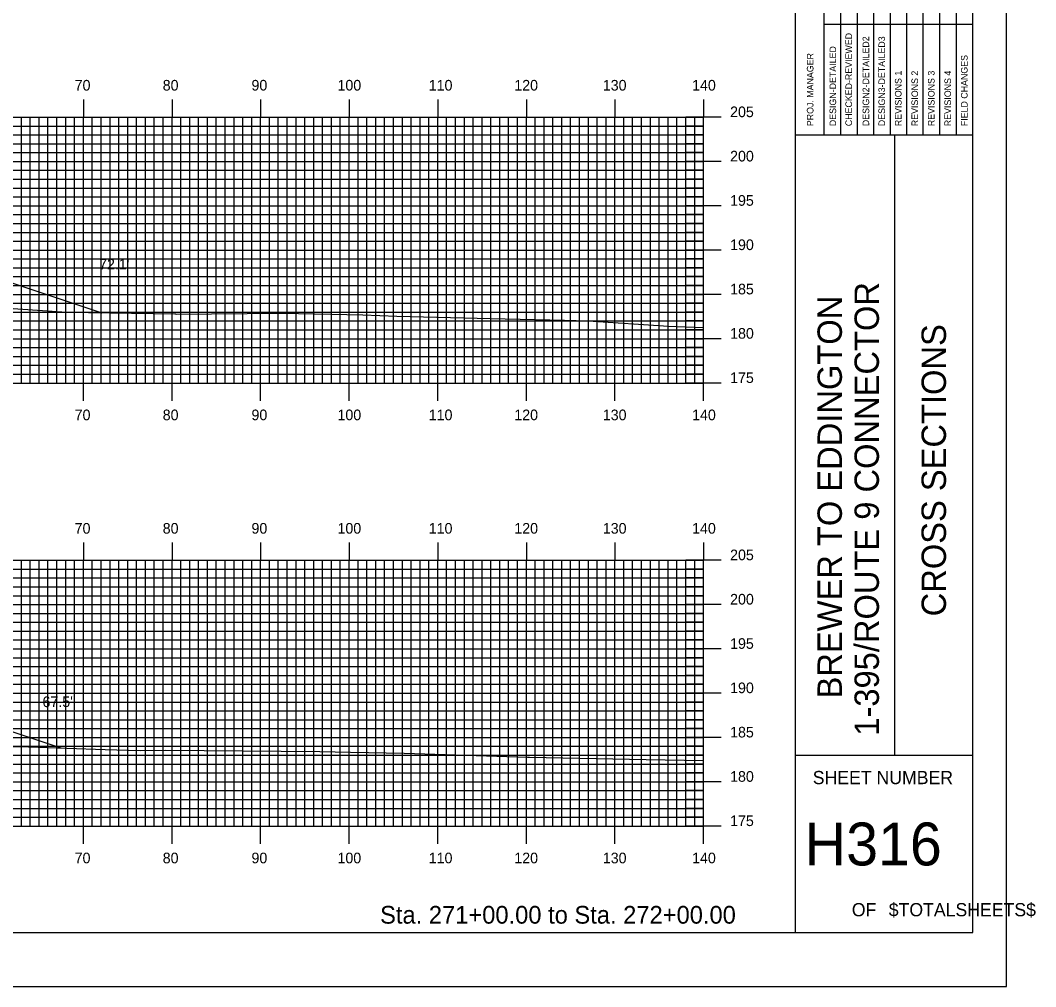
# Model space of a CAD drawing. Extents: x 1808619 to 1808962, y 442591 to 442811.
# Drawn here: x 1808847.7 to 1808962.3, y 442590.5 to 442699.6 of the extents above; entities that cross this region are included whole.
import ezdxf

# ---------------------------------------------------------------- set-up
doc = ezdxf.new("R2010")
doc.units = 0
for name, color, linetype in [('BORDER', 7, 'Continuous'), ('D_Roadway_Centerline', 7, 'Continuous'), ('D_Roadway_SlopeLines', 7, 'Continuous'), ('D_Text_Standard', 7, 'Continuous'), ('H_V ANNOTATION', 7, 'Continuous'), ('MAJOR', 7, 'Continuous'), ('MINOR', 7, 'Continuous'), ('PLOT BOUNDARY', 7, 'Continuous'), ('S_Roadway_Centerline', 7, 'Continuous')]:
    doc.layers.add(name, color=color, linetype=linetype)

msp = doc.modelspace()

# ---------------------------------------------------------------- linework, layer by layer
at = {"layer": 'BORDER'}
for p, q in [((1808935.21, 442596.67), (1808935.21, 442806.67)), ((1808935.21, 442686.67), (1808955.21, 442686.67)), ((1808946.39, 442616.67), (1808946.39, 442686.67)), ((1808935.21, 442616.67), (1808955.21, 442616.67))]:
    msp.add_line(p, q, dxfattribs=at)
msp.add_lwpolyline([(1808635.21, 442596.67), (1808955.21, 442596.67), (1808955.21, 442806.67), (1808635.21, 442806.67)], close=True, dxfattribs=at)
for points in [[(1808940.31, 442686.68), (1808940.31, 442721.67)], [(1808942.17, 442721.67), (1808942.17, 442686.68)], [(1808944.03, 442686.68), (1808944.03, 442721.67)], [(1808945.9, 442686.68), (1808945.9, 442721.67)], [(1808947.76, 442686.68), (1808947.76, 442721.67)], [(1808949.62, 442686.68), (1808949.62, 442721.67)], [(1808951.49, 442686.68), (1808951.49, 442721.67)], [(1808953.35, 442686.68), (1808953.35, 442721.67)], [(1808938.44, 442686.68), (1808938.44, 442720.26)], [(1808938.44, 442699.17), (1808955.21, 442699.17)]]:
    msp.add_lwpolyline(points, dxfattribs=at)
at = {"layer": 'D_Roadway_Centerline'}
for points in [[(1808717.59, 442667.84), (1808754.72, 442680.52), (1808761.81, 442682.94), (1808764.81, 442683.06), (1808772.81, 442683.38), (1808784.81, 442683.62), (1808796.81, 442683.38), (1808804.81, 442683.06), (1808807.81, 442682.94), (1808815.09, 442680.52), (1808856.88, 442666.59)], [(1808713.91, 442618.99), (1808744.23, 442629.09), (1808746.8, 442629.73), (1808756.23, 442632.09), (1808772.81, 442632.75), (1808784.81, 442632.99), (1808796.81, 442632.75), (1808804.81, 442632.43), (1808807.81, 442632.31), (1808815.09, 442629.89), (1808852.27, 442617.49)]]:
    msp.add_lwpolyline(points, dxfattribs=at)
at = {"layer": 'D_Roadway_SlopeLines'}
for points in [[(1808807.81, 442682.94), (1808856.88, 442666.59)], [(1808807.81, 442632.31), (1808852.27, 442617.49)]]:
    msp.add_lwpolyline(points, dxfattribs=at)
at = {"layer": 'MAJOR'}
for p, q in [((1808854.81, 442690.67), (1808854.81, 442688.67)), ((1808864.81, 442690.67), (1808864.81, 442688.67)), ((1808874.81, 442690.67), (1808874.81, 442688.67)), ((1808884.81, 442690.67), (1808884.81, 442688.67)), ((1808894.81, 442690.67), (1808894.81, 442688.67)), ((1808904.81, 442690.67), (1808904.81, 442688.67)), ((1808914.81, 442690.67), (1808914.81, 442688.67)), ((1808924.81, 442690.67), (1808924.81, 442688.67)), ((1808644.81, 442688.67), (1808924.81, 442688.67)), ((1808644.81, 442688.67), (1808924.81, 442688.67)), ((1808854.81, 442658.67), (1808854.81, 442688.67)), ((1808864.81, 442658.67), (1808864.81, 442688.67)), ((1808874.81, 442658.67), (1808874.81, 442688.67)), ((1808884.81, 442658.67), (1808884.81, 442688.67)), ((1808894.81, 442658.67), (1808894.81, 442688.67)), ((1808904.81, 442658.67), (1808904.81, 442688.67)), ((1808914.81, 442658.67), (1808914.81, 442688.67)), ((1808926.82, 442688.67), (1808922.81, 442688.67)), ((1808924.81, 442658.67), (1808924.81, 442688.67)), ((1808924.81, 442658.67), (1808924.81, 442688.67)), ((1808644.81, 442683.67), (1808924.81, 442683.67)), ((1808926.82, 442683.67), (1808922.81, 442683.67)), ((1808644.81, 442678.67), (1808924.81, 442678.67)), ((1808926.82, 442678.67), (1808922.81, 442678.67)), ((1808644.81, 442673.67), (1808924.81, 442673.67)), ((1808926.82, 442673.67), (1808922.81, 442673.67)), ((1808644.81, 442668.67), (1808924.81, 442668.67)), ((1808926.82, 442668.67), (1808922.81, 442668.67)), ((1808644.81, 442663.67), (1808924.81, 442663.67)), ((1808926.82, 442663.67), (1808922.81, 442663.67)), ((1808644.81, 442658.67), (1808924.81, 442658.67)), ((1808644.81, 442658.67), (1808924.81, 442658.67)), ((1808854.81, 442656.66), (1808854.81, 442658.67)), ((1808864.81, 442656.66), (1808864.81, 442658.67)), ((1808874.81, 442656.66), (1808874.81, 442658.67)), ((1808884.81, 442656.66), (1808884.81, 442658.67)), ((1808894.81, 442656.66), (1808894.81, 442658.67)), ((1808904.81, 442656.66), (1808904.81, 442658.67)), ((1808914.81, 442656.66), (1808914.81, 442658.67)), ((1808926.82, 442658.67), (1808922.81, 442658.67)), ((1808924.81, 442656.66), (1808924.81, 442658.67)), ((1808854.81, 442640.67), (1808854.81, 442638.67)), ((1808864.81, 442640.67), (1808864.81, 442638.67)), ((1808874.81, 442640.67), (1808874.81, 442638.67)), ((1808884.81, 442640.67), (1808884.81, 442638.67)), ((1808894.81, 442640.67), (1808894.81, 442638.67)), ((1808904.81, 442640.67), (1808904.81, 442638.67)), ((1808914.81, 442640.67), (1808914.81, 442638.67)), ((1808924.81, 442640.67), (1808924.81, 442638.67)), ((1808644.81, 442638.67), (1808924.81, 442638.67)), ((1808644.81, 442638.67), (1808924.81, 442638.67)), ((1808854.81, 442608.67), (1808854.81, 442638.67)), ((1808864.81, 442608.67), (1808864.81, 442638.67)), ((1808874.81, 442608.67), (1808874.81, 442638.67)), ((1808884.81, 442608.67), (1808884.81, 442638.67)), ((1808894.81, 442608.67), (1808894.81, 442638.67)), ((1808904.81, 442608.67), (1808904.81, 442638.67)), ((1808914.81, 442608.67), (1808914.81, 442638.67)), ((1808926.82, 442638.67), (1808922.81, 442638.67)), ((1808924.81, 442608.67), (1808924.81, 442638.67)), ((1808924.81, 442608.67), (1808924.81, 442638.67)), ((1808644.81, 442633.67), (1808924.81, 442633.67)), ((1808926.82, 442633.67), (1808922.81, 442633.67)), ((1808644.81, 442628.67), (1808924.81, 442628.67)), ((1808926.82, 442628.67), (1808922.81, 442628.67)), ((1808644.81, 442623.67), (1808924.81, 442623.67)), ((1808926.82, 442623.67), (1808922.81, 442623.67)), ((1808644.81, 442618.67), (1808924.81, 442618.67)), ((1808926.82, 442618.67), (1808922.81, 442618.67)), ((1808644.81, 442613.67), (1808924.81, 442613.67)), ((1808926.82, 442613.67), (1808922.81, 442613.67)), ((1808644.81, 442608.67), (1808924.81, 442608.67)), ((1808644.81, 442608.67), (1808924.81, 442608.67)), ((1808854.81, 442606.66), (1808854.81, 442608.67)), ((1808864.81, 442606.66), (1808864.81, 442608.67)), ((1808874.81, 442606.66), (1808874.81, 442608.67)), ((1808884.81, 442606.66), (1808884.81, 442608.67)), ((1808894.81, 442606.66), (1808894.81, 442608.67)), ((1808904.81, 442606.66), (1808904.81, 442608.67)), ((1808914.81, 442606.66), (1808914.81, 442608.67)), ((1808926.82, 442608.67), (1808922.81, 442608.67)), ((1808924.81, 442606.66), (1808924.81, 442608.67))]:
    msp.add_line(p, q, dxfattribs=at)
at = {"layer": 'MINOR'}
for p, q in [((1808644.81, 442687.67), (1808924.81, 442687.67)), ((1808847.81, 442658.67), (1808847.81, 442688.67)), ((1808848.81, 442658.67), (1808848.81, 442688.67)), ((1808849.81, 442658.67), (1808849.81, 442688.67)), ((1808850.81, 442658.67), (1808850.81, 442688.67)), ((1808851.81, 442658.67), (1808851.81, 442688.67)), ((1808852.81, 442658.67), (1808852.81, 442688.67)), ((1808853.81, 442658.67), (1808853.81, 442688.67)), ((1808855.81, 442658.67), (1808855.81, 442688.67)), ((1808856.81, 442658.67), (1808856.81, 442688.67)), ((1808857.81, 442658.67), (1808857.81, 442688.67)), ((1808858.81, 442658.67), (1808858.81, 442688.67)), ((1808859.81, 442658.67), (1808859.81, 442688.67)), ((1808860.81, 442658.67), (1808860.81, 442688.67)), ((1808861.81, 442658.67), (1808861.81, 442688.67)), ((1808862.81, 442658.67), (1808862.81, 442688.67)), ((1808863.81, 442658.67), (1808863.81, 442688.67)), ((1808865.81, 442658.67), (1808865.81, 442688.67)), ((1808866.81, 442658.67), (1808866.81, 442688.67)), ((1808867.81, 442658.67), (1808867.81, 442688.67)), ((1808868.81, 442658.67), (1808868.81, 442688.67)), ((1808869.81, 442658.67), (1808869.81, 442688.67)), ((1808870.81, 442658.67), (1808870.81, 442688.67)), ((1808871.81, 442658.67), (1808871.81, 442688.67)), ((1808872.81, 442658.67), (1808872.81, 442688.67)), ((1808873.81, 442658.67), (1808873.81, 442688.67)), ((1808875.81, 442658.67), (1808875.81, 442688.67)), ((1808876.81, 442658.67), (1808876.81, 442688.67)), ((1808877.81, 442658.67), (1808877.81, 442688.67)), ((1808878.81, 442658.67), (1808878.81, 442688.67)), ((1808879.81, 442658.67), (1808879.81, 442688.67)), ((1808880.81, 442658.67), (1808880.81, 442688.67)), ((1808881.81, 442658.67), (1808881.81, 442688.67)), ((1808882.81, 442658.67), (1808882.81, 442688.67)), ((1808883.81, 442658.67), (1808883.81, 442688.67)), ((1808885.81, 442658.67), (1808885.81, 442688.67)), ((1808886.81, 442658.67), (1808886.81, 442688.67)), ((1808887.81, 442658.67), (1808887.81, 442688.67)), ((1808888.81, 442658.67), (1808888.81, 442688.67)), ((1808889.81, 442658.67), (1808889.81, 442688.67)), ((1808890.81, 442658.67), (1808890.81, 442688.67)), ((1808891.81, 442658.67), (1808891.81, 442688.67)), ((1808892.81, 442658.67), (1808892.81, 442688.67)), ((1808893.81, 442658.67), (1808893.81, 442688.67)), ((1808895.81, 442658.67), (1808895.81, 442688.67)), ((1808896.81, 442658.67), (1808896.81, 442688.67)), ((1808897.81, 442658.67), (1808897.81, 442688.67)), ((1808898.81, 442658.67), (1808898.81, 442688.67)), ((1808899.81, 442658.67), (1808899.81, 442688.67)), ((1808900.81, 442658.67), (1808900.81, 442688.67)), ((1808901.81, 442658.67), (1808901.81, 442688.67)), ((1808902.81, 442658.67), (1808902.81, 442688.67)), ((1808903.81, 442658.67), (1808903.81, 442688.67)), ((1808905.81, 442658.67), (1808905.81, 442688.67)), ((1808906.81, 442658.67), (1808906.81, 442688.67)), ((1808907.81, 442658.67), (1808907.81, 442688.67)), ((1808908.81, 442658.67), (1808908.81, 442688.67)), ((1808909.81, 442658.67), (1808909.81, 442688.67)), ((1808910.81, 442658.67), (1808910.81, 442688.67)), ((1808911.81, 442658.67), (1808911.81, 442688.67)), ((1808912.81, 442658.67), (1808912.81, 442688.67)), ((1808913.81, 442658.67), (1808913.81, 442688.67)), ((1808915.81, 442658.67), (1808915.81, 442688.67)), ((1808916.81, 442658.67), (1808916.81, 442688.67)), ((1808917.81, 442658.67), (1808917.81, 442688.67)), ((1808918.81, 442658.67), (1808918.81, 442688.67)), ((1808919.81, 442658.67), (1808919.81, 442688.67)), ((1808920.81, 442658.67), (1808920.81, 442688.67)), ((1808921.81, 442658.67), (1808921.81, 442688.67)), ((1808922.81, 442658.67), (1808922.81, 442688.67)), ((1808924.81, 442687.67), (1808922.81, 442687.67)), ((1808923.81, 442658.67), (1808923.81, 442688.67)), ((1808644.81, 442686.67), (1808924.81, 442686.67)), ((1808924.81, 442686.67), (1808922.81, 442686.67)), ((1808644.81, 442685.67), (1808924.81, 442685.67)), ((1808924.81, 442685.67), (1808922.81, 442685.67)), ((1808644.81, 442684.67), (1808924.81, 442684.67)), ((1808924.81, 442684.67), (1808922.81, 442684.67)), ((1808644.81, 442682.67), (1808924.81, 442682.67)), ((1808924.81, 442682.67), (1808922.81, 442682.67)), ((1808644.81, 442681.67), (1808924.81, 442681.67)), ((1808924.81, 442681.67), (1808922.81, 442681.67)), ((1808644.81, 442680.67), (1808924.81, 442680.67)), ((1808644.81, 442679.67), (1808924.81, 442679.67)), ((1808924.81, 442680.67), (1808922.81, 442680.67)), ((1808924.81, 442679.67), (1808922.81, 442679.67)), ((1808644.81, 442677.67), (1808924.81, 442677.67)), ((1808924.81, 442677.67), (1808922.81, 442677.67)), ((1808644.81, 442676.67), (1808924.81, 442676.67)), ((1808924.81, 442676.67), (1808922.81, 442676.67)), ((1808644.81, 442675.67), (1808924.81, 442675.67)), ((1808924.81, 442675.67), (1808922.81, 442675.67)), ((1808644.81, 442674.67), (1808924.81, 442674.67)), ((1808924.81, 442674.67), (1808922.81, 442674.67)), ((1808644.81, 442672.67), (1808924.81, 442672.67)), ((1808644.81, 442671.67), (1808924.81, 442671.67)), ((1808924.81, 442672.67), (1808922.81, 442672.67)), ((1808924.81, 442671.67), (1808922.81, 442671.67)), ((1808644.81, 442670.67), (1808924.81, 442670.67)), ((1808924.81, 442670.67), (1808922.81, 442670.67)), ((1808644.81, 442669.67), (1808924.81, 442669.67)), ((1808924.81, 442669.67), (1808922.81, 442669.67)), ((1808644.81, 442667.67), (1808924.81, 442667.67)), ((1808924.81, 442667.67), (1808922.81, 442667.67)), ((1808644.81, 442666.67), (1808924.81, 442666.67)), ((1808924.81, 442666.67), (1808922.81, 442666.67)), ((1808644.81, 442665.67), (1808924.81, 442665.67)), ((1808924.81, 442665.67), (1808922.81, 442665.67)), ((1808644.81, 442664.67), (1808924.81, 442664.67)), ((1808924.81, 442664.67), (1808922.81, 442664.67)), ((1808644.81, 442662.67), (1808924.81, 442662.67)), ((1808924.81, 442662.67), (1808922.81, 442662.67)), ((1808644.81, 442661.67), (1808924.81, 442661.67)), ((1808924.81, 442661.67), (1808922.81, 442661.67)), ((1808644.81, 442660.67), (1808924.81, 442660.67)), ((1808924.81, 442660.67), (1808922.81, 442660.67)), ((1808644.81, 442659.67), (1808924.81, 442659.67)), ((1808924.81, 442659.67), (1808922.81, 442659.67)), ((1808847.81, 442608.67), (1808847.81, 442638.67)), ((1808848.81, 442608.67), (1808848.81, 442638.67)), ((1808849.81, 442608.67), (1808849.81, 442638.67)), ((1808850.81, 442608.67), (1808850.81, 442638.67)), ((1808851.81, 442608.67), (1808851.81, 442638.67)), ((1808852.81, 442608.67), (1808852.81, 442638.67)), ((1808853.81, 442608.67), (1808853.81, 442638.67)), ((1808855.81, 442608.67), (1808855.81, 442638.67)), ((1808856.81, 442608.67), (1808856.81, 442638.67)), ((1808857.81, 442608.67), (1808857.81, 442638.67)), ((1808858.81, 442608.67), (1808858.81, 442638.67)), ((1808859.81, 442608.67), (1808859.81, 442638.67)), ((1808860.81, 442608.67), (1808860.81, 442638.67)), ((1808861.81, 442608.67), (1808861.81, 442638.67)), ((1808862.81, 442608.67), (1808862.81, 442638.67)), ((1808863.81, 442608.67), (1808863.81, 442638.67)), ((1808865.81, 442608.67), (1808865.81, 442638.67)), ((1808866.81, 442608.67), (1808866.81, 442638.67)), ((1808867.81, 442608.67), (1808867.81, 442638.67)), ((1808868.81, 442608.67), (1808868.81, 442638.67)), ((1808869.81, 442608.67), (1808869.81, 442638.67)), ((1808870.81, 442608.67), (1808870.81, 442638.67)), ((1808871.81, 442608.67), (1808871.81, 442638.67)), ((1808872.81, 442608.67), (1808872.81, 442638.67)), ((1808873.81, 442608.67), (1808873.81, 442638.67)), ((1808875.81, 442608.67), (1808875.81, 442638.67)), ((1808876.81, 442608.67), (1808876.81, 442638.67)), ((1808877.81, 442608.67), (1808877.81, 442638.67)), ((1808878.81, 442608.67), (1808878.81, 442638.67)), ((1808879.81, 442608.67), (1808879.81, 442638.67)), ((1808880.81, 442608.67), (1808880.81, 442638.67)), ((1808881.81, 442608.67), (1808881.81, 442638.67)), ((1808882.81, 442608.67), (1808882.81, 442638.67)), ((1808883.81, 442608.67), (1808883.81, 442638.67)), ((1808885.81, 442608.67), (1808885.81, 442638.67)), ((1808886.81, 442608.67), (1808886.81, 442638.67)), ((1808887.81, 442608.67), (1808887.81, 442638.67)), ((1808888.81, 442608.67), (1808888.81, 442638.67)), ((1808889.81, 442608.67), (1808889.81, 442638.67)), ((1808890.81, 442608.67), (1808890.81, 442638.67)), ((1808891.81, 442608.67), (1808891.81, 442638.67)), ((1808892.81, 442608.67), (1808892.81, 442638.67)), ((1808893.81, 442608.67), (1808893.81, 442638.67)), ((1808895.81, 442608.67), (1808895.81, 442638.67)), ((1808896.81, 442608.67), (1808896.81, 442638.67)), ((1808897.81, 442608.67), (1808897.81, 442638.67)), ((1808898.81, 442608.67), (1808898.81, 442638.67)), ((1808899.81, 442608.67), (1808899.81, 442638.67)), ((1808900.81, 442608.67), (1808900.81, 442638.67)), ((1808901.81, 442608.67), (1808901.81, 442638.67)), ((1808902.81, 442608.67), (1808902.81, 442638.67)), ((1808903.81, 442608.67), (1808903.81, 442638.67)), ((1808905.81, 442608.67), (1808905.81, 442638.67)), ((1808906.81, 442608.67), (1808906.81, 442638.67)), ((1808907.81, 442608.67), (1808907.81, 442638.67)), ((1808908.81, 442608.67), (1808908.81, 442638.67)), ((1808909.81, 442608.67), (1808909.81, 442638.67)), ((1808910.81, 442608.67), (1808910.81, 442638.67)), ((1808911.81, 442608.67), (1808911.81, 442638.67)), ((1808912.81, 442608.67), (1808912.81, 442638.67)), ((1808913.81, 442608.67), (1808913.81, 442638.67)), ((1808915.81, 442608.67), (1808915.81, 442638.67)), ((1808916.81, 442608.67), (1808916.81, 442638.67)), ((1808917.81, 442608.67), (1808917.81, 442638.67)), ((1808918.81, 442608.67), (1808918.81, 442638.67)), ((1808919.81, 442608.67), (1808919.81, 442638.67)), ((1808920.81, 442608.67), (1808920.81, 442638.67)), ((1808921.81, 442608.67), (1808921.81, 442638.67)), ((1808922.81, 442608.67), (1808922.81, 442638.67)), ((1808923.81, 442608.67), (1808923.81, 442638.67)), ((1808644.81, 442637.67), (1808924.81, 442637.67)), ((1808924.81, 442637.67), (1808922.81, 442637.67)), ((1808644.81, 442636.67), (1808924.81, 442636.67)), ((1808924.81, 442636.67), (1808922.81, 442636.67)), ((1808644.81, 442635.67), (1808924.81, 442635.67)), ((1808924.81, 442635.67), (1808922.81, 442635.67)), ((1808644.81, 442634.67), (1808924.81, 442634.67)), ((1808924.81, 442634.67), (1808922.81, 442634.67)), ((1808644.81, 442632.67), (1808924.81, 442632.67)), ((1808924.81, 442632.67), (1808922.81, 442632.67)), ((1808644.81, 442631.67), (1808924.81, 442631.67)), ((1808924.81, 442631.67), (1808922.81, 442631.67)), ((1808644.81, 442630.67), (1808924.81, 442630.67)), ((1808924.81, 442630.67), (1808922.81, 442630.67)), ((1808644.81, 442629.67), (1808924.81, 442629.67)), ((1808924.81, 442629.67), (1808922.81, 442629.67)), ((1808644.81, 442627.67), (1808924.81, 442627.67)), ((1808924.81, 442627.67), (1808922.81, 442627.67)), ((1808644.81, 442626.67), (1808924.81, 442626.67)), ((1808924.81, 442626.67), (1808922.81, 442626.67)), ((1808644.81, 442625.67), (1808924.81, 442625.67)), ((1808644.81, 442624.67), (1808924.81, 442624.67)), ((1808924.81, 442625.67), (1808922.81, 442625.67)), ((1808924.81, 442624.67), (1808922.81, 442624.67)), ((1808644.81, 442622.67), (1808924.81, 442622.67)), ((1808924.81, 442622.67), (1808922.81, 442622.67)), ((1808644.81, 442621.67), (1808924.81, 442621.67)), ((1808924.81, 442621.67), (1808922.81, 442621.67)), ((1808644.81, 442620.67), (1808924.81, 442620.67)), ((1808924.81, 442620.67), (1808922.81, 442620.67)), ((1808644.81, 442619.67), (1808924.81, 442619.67)), ((1808924.81, 442619.67), (1808922.81, 442619.67)), ((1808644.81, 442617.67), (1808924.81, 442617.67)), ((1808644.81, 442616.67), (1808924.81, 442616.67)), ((1808924.81, 442617.67), (1808922.81, 442617.67)), ((1808924.81, 442616.67), (1808922.81, 442616.67)), ((1808644.81, 442615.67), (1808924.81, 442615.67)), ((1808924.81, 442615.67), (1808922.81, 442615.67)), ((1808644.81, 442614.67), (1808924.81, 442614.67)), ((1808924.81, 442614.67), (1808922.81, 442614.67)), ((1808644.81, 442612.67), (1808924.81, 442612.67)), ((1808924.81, 442612.67), (1808922.81, 442612.67)), ((1808644.81, 442611.67), (1808924.81, 442611.67)), ((1808924.81, 442611.67), (1808922.81, 442611.67)), ((1808644.81, 442610.67), (1808924.81, 442610.67)), ((1808924.81, 442610.67), (1808922.81, 442610.67)), ((1808644.81, 442609.67), (1808924.81, 442609.67)), ((1808924.81, 442609.67), (1808922.81, 442609.67))]:
    msp.add_line(p, q, dxfattribs=at)
at = {"layer": 'PLOT BOUNDARY'}
msp.add_lwpolyline([(1808619.02, 442590.55), (1808959.02, 442590.55), (1808959.02, 442810.55), (1808619.02, 442810.55)], close=True, dxfattribs=at)
at = {"layer": 'S_Roadway_Centerline'}
for points in [[(1808844.63, 442667.21), (1808852.92, 442666.65), (1808865.12, 442666.46), (1808865.21, 442666.46), (1808865.28, 442666.45), (1808877.28, 442666.55), (1808886.34, 442666.37), (1808890.19, 442666.21), (1808900.77, 442665.96), (1808909.12, 442665.76), (1808911.79, 442665.69), (1808920.85, 442665.07), (1808924.81, 442664.94)], [(1808842.48, 442617.66), (1808848.6, 442617.62), (1808857.25, 442617.32), (1808861.21, 442617.19), (1808864.09, 442617.23), (1808881.48, 442617.08), (1808884.96, 442617.03), (1808891.02, 442616.91), (1808904.93, 442616.44), (1808905.06, 442616.43), (1808905.18, 442616.43), (1808918.35, 442616.2), (1808924.81, 442616.08)]]:
    msp.add_lwpolyline(points, dxfattribs=at)

# ---------------------------------------------------------------- texts
at = {"layer": 'BORDER'}
for s, height, p in [('CHECKED-REVIEWED', 0.7455, (1808941.57, 442687.65)), ('DESIGN2-DETAILED2', 0.7455, (1808943.51, 442687.65)), ('DESIGN3-DETAILED3', 0.7455, (1808945.3, 442687.65)), ('PROJ. MANAGER', 0.7455, (1808937.22, 442687.65)), ('DESIGN-DETAILED', 0.7455, (1808939.78, 442687.65)), ('FIELD CHANGES', 0.7455, (1808954.62, 442687.65)), ('REVISIONS 1', 0.7455, (1808947.16, 442687.65)), ('REVISIONS 2', 0.7455, (1808949.03, 442687.65)), ('REVISIONS 3', 0.7455, (1808950.89, 442687.65)), ('REVISIONS 4', 0.7455, (1808952.75, 442687.65)), ('1-395/ROUTE 9 CONNECTOR', 2.7557, (1808944.61, 442618.87)), ('BREWER TO EDDINGTON', 2.7557, (1808940.43, 442623.07)), ('CROSS SECTIONS', 2.7557, (1808952.18, 442632.34))]:
    msp.add_text(s, height=height, rotation=90, dxfattribs=at).set_placement(p)
for s, height, p in [('SHEET NUMBER', 1.4905, (1808937.14, 442613.4)), ('H316', 4.839, (1808936.24, 442604.23)), ('OF', 1.491, (1808941.55, 442598.49)), ('$TOTALSHEETS$', 1.4905, (1808945.72, 442598.49))]:
    msp.add_text(s, height=height, dxfattribs=at).set_placement(p)
at = {"layer": 'D_Text_Standard'}
for s, p in [("72.1'", (1808856.58, 442671.48)), ("67.5'", (1808850.19, 442622.1))]:
    msp.add_text(s, height=1.2, dxfattribs=at).set_placement(p)
at = {"layer": 'H_V ANNOTATION'}
for s, height, p in [('70', 1.2, (1808853.82, 442691.67)), ('80', 1.2, (1808863.76, 442691.67)), ('90', 1.2, (1808873.78, 442691.67)), ('100', 1.2, (1808883.49, 442691.67)), ('110', 1.2, (1808893.79, 442691.67)), ('120', 1.2, (1808903.45, 442691.67)), ('130', 1.2, (1808913.44, 442691.67)), ('140', 1.2, (1808923.52, 442691.67)), ('205', 1.2, (1808927.81, 442688.67)), ('200', 1.2, (1808927.81, 442683.67)), ('195', 1.2, (1808927.81, 442678.67)), ('190', 1.2, (1808927.81, 442673.67)), ('185', 1.2, (1808927.81, 442668.67)), ('180', 1.2, (1808927.81, 442663.67)), ('175', 1.2, (1808927.81, 442658.67)), ('70', 1.2, (1808853.82, 442654.47)), ('80', 1.2, (1808863.76, 442654.47)), ('90', 1.2, (1808873.78, 442654.47)), ('100', 1.2, (1808883.49, 442654.47)), ('110', 1.2, (1808893.79, 442654.47)), ('120', 1.2, (1808903.45, 442654.47)), ('130', 1.2, (1808913.44, 442654.47)), ('140', 1.2, (1808923.52, 442654.47)), ('70', 1.2, (1808853.82, 442641.67)), ('80', 1.2, (1808863.76, 442641.67)), ('90', 1.2, (1808873.78, 442641.67)), ('100', 1.2, (1808883.49, 442641.67)), ('110', 1.2, (1808893.79, 442641.67)), ('120', 1.2, (1808903.45, 442641.67)), ('130', 1.2, (1808913.44, 442641.67)), ('140', 1.2, (1808923.52, 442641.67)), ('205', 1.2, (1808927.81, 442638.67)), ('200', 1.2, (1808927.81, 442633.67)), ('195', 1.2, (1808927.81, 442628.67)), ('190', 1.2, (1808927.81, 442623.67)), ('185', 1.2, (1808927.81, 442618.67)), ('180', 1.2, (1808927.81, 442613.67)), ('175', 1.2, (1808927.81, 442608.67)), ('70', 1.2, (1808853.82, 442604.47)), ('80', 1.2, (1808863.76, 442604.47)), ('90', 1.2, (1808873.78, 442604.47)), ('100', 1.2, (1808883.49, 442604.47)), ('110', 1.2, (1808893.79, 442604.47)), ('120', 1.2, (1808903.45, 442604.47)), ('130', 1.2, (1808913.44, 442604.47)), ('140', 1.2, (1808923.52, 442604.47)), ('Sta. 271+00.00 to Sta. 272+00.00', 2.0004, (1808888.3, 442597.66))]:
    msp.add_text(s, height=height, dxfattribs=at).set_placement(p)

doc.saveas('drawing.dxf')
